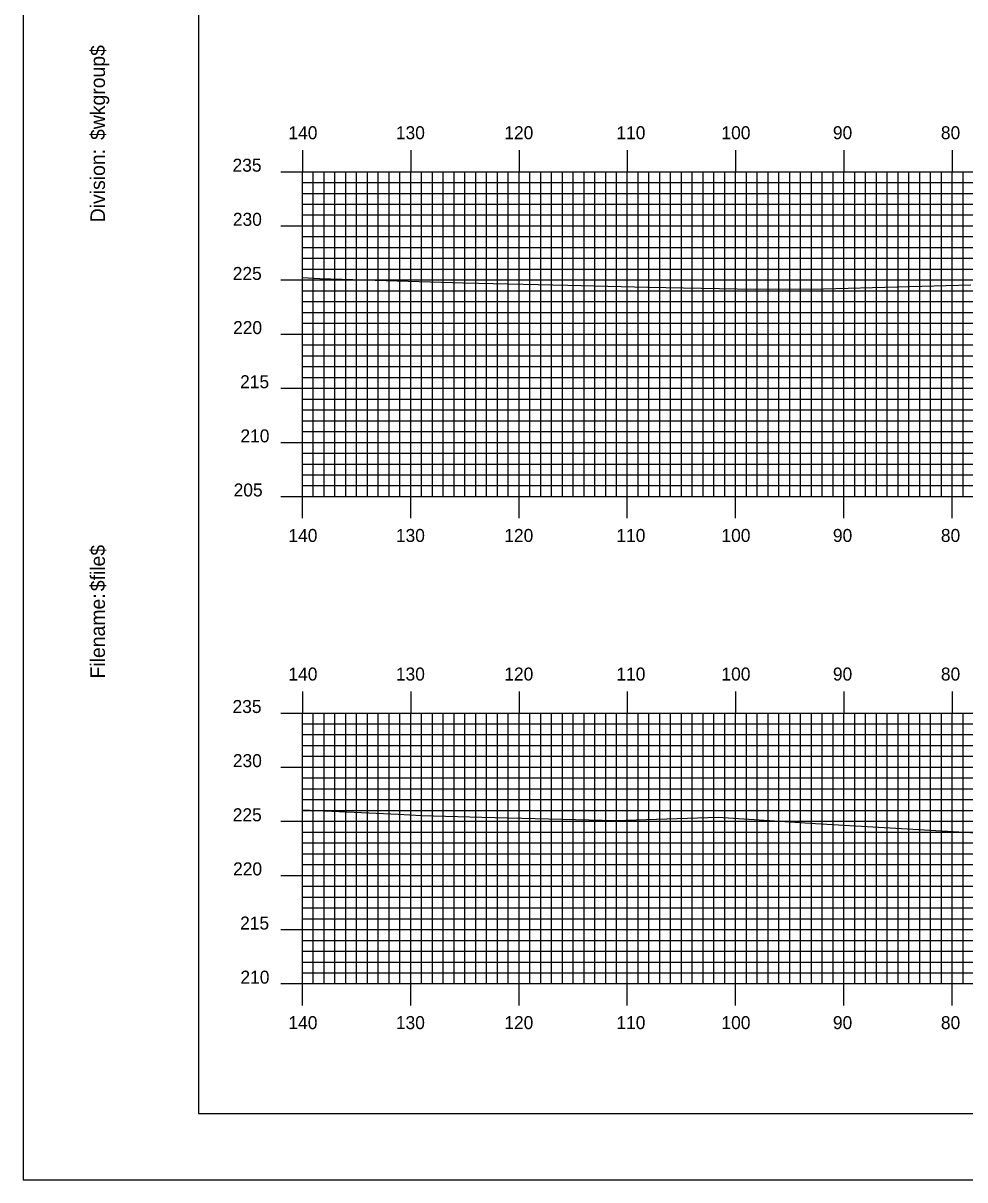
# Model space of a CAD drawing. Extents: x 1820424 to 1820768, y 442591 to 442811.
# Drawn here: x 1820424.4 to 1820511.4, y 442590.5 to 442697.4 of the extents above; entities that cross this region are included whole.
import ezdxf

# ---------------------------------------------------------------- set-up
doc = ezdxf.new("R2010")
doc.units = 0
for name, color, linetype in [('BORDER', 7, 'Continuous'), ('H_V ANNOTATION', 7, 'Continuous'), ('MAJOR', 7, 'Continuous'), ('MINOR', 7, 'Continuous'), ('PLOT BOUNDARY', 7, 'Continuous'), ('S_Roadway_Centerline', 7, 'Continuous')]:
    doc.layers.add(name, color=color, linetype=linetype)

msp = doc.modelspace()

# ---------------------------------------------------------------- linework, layer by layer
at = {"layer": 'BORDER'}
msp.add_lwpolyline([(1820440.6, 442596.67), (1820760.6, 442596.67), (1820760.6, 442806.67), (1820440.6, 442806.67)], close=True, dxfattribs=at)
at = {"layer": 'MAJOR'}
for p, q in [((1820450.2, 442685.67), (1820450.2, 442683.67)), ((1820460.2, 442685.67), (1820460.2, 442683.67)), ((1820470.2, 442685.67), (1820470.2, 442683.67)), ((1820480.2, 442685.67), (1820480.2, 442683.67)), ((1820490.2, 442685.67), (1820490.2, 442683.67)), ((1820500.2, 442685.67), (1820500.2, 442683.67)), ((1820510.2, 442685.67), (1820510.2, 442683.67)), ((1820448.2, 442683.67), (1820450.2, 442683.67)), ((1820450.2, 442683.67), (1820730.2, 442683.67)), ((1820450.2, 442653.67), (1820450.2, 442683.67)), ((1820450.2, 442653.67), (1820450.2, 442683.67)), ((1820450.2, 442683.67), (1820730.2, 442683.67)), ((1820460.2, 442653.67), (1820460.2, 442683.67)), ((1820470.2, 442653.67), (1820470.2, 442683.67)), ((1820480.2, 442653.67), (1820480.2, 442683.67)), ((1820490.2, 442653.67), (1820490.2, 442683.67)), ((1820500.2, 442653.67), (1820500.2, 442683.67)), ((1820510.2, 442653.67), (1820510.2, 442683.67)), ((1820448.2, 442678.67), (1820450.2, 442678.67)), ((1820450.2, 442678.67), (1820730.2, 442678.67)), ((1820448.2, 442673.67), (1820450.2, 442673.67)), ((1820450.2, 442673.67), (1820730.2, 442673.67)), ((1820448.2, 442668.67), (1820450.2, 442668.67)), ((1820450.2, 442668.67), (1820730.2, 442668.67)), ((1820448.2, 442663.67), (1820450.2, 442663.67)), ((1820450.2, 442663.67), (1820730.2, 442663.67)), ((1820448.2, 442658.67), (1820450.2, 442658.67)), ((1820450.2, 442658.67), (1820730.2, 442658.67)), ((1820448.2, 442653.67), (1820450.2, 442653.67)), ((1820450.2, 442653.67), (1820730.2, 442653.67)), ((1820450.2, 442653.67), (1820730.2, 442653.67)), ((1820450.2, 442651.66), (1820450.2, 442653.67)), ((1820460.2, 442651.66), (1820460.2, 442653.67)), ((1820470.2, 442651.66), (1820470.2, 442653.67)), ((1820480.2, 442651.66), (1820480.2, 442653.67)), ((1820490.2, 442651.66), (1820490.2, 442653.67)), ((1820500.2, 442651.66), (1820500.2, 442653.67)), ((1820510.2, 442651.66), (1820510.2, 442653.67)), ((1820450.2, 442635.67), (1820450.2, 442633.67)), ((1820460.2, 442635.67), (1820460.2, 442633.67)), ((1820470.2, 442635.67), (1820470.2, 442633.67)), ((1820480.2, 442635.67), (1820480.2, 442633.67)), ((1820490.2, 442635.67), (1820490.2, 442633.67)), ((1820500.2, 442635.67), (1820500.2, 442633.67)), ((1820510.2, 442635.67), (1820510.2, 442633.67)), ((1820448.2, 442633.67), (1820450.2, 442633.67)), ((1820450.2, 442633.67), (1820730.2, 442633.67)), ((1820450.2, 442608.67), (1820450.2, 442633.67)), ((1820450.2, 442608.67), (1820450.2, 442633.67)), ((1820450.2, 442633.67), (1820730.2, 442633.67)), ((1820460.2, 442608.67), (1820460.2, 442633.67)), ((1820470.2, 442608.67), (1820470.2, 442633.67)), ((1820480.2, 442608.67), (1820480.2, 442633.67)), ((1820490.2, 442608.67), (1820490.2, 442633.67)), ((1820500.2, 442608.67), (1820500.2, 442633.67)), ((1820510.2, 442608.67), (1820510.2, 442633.67)), ((1820448.2, 442628.67), (1820450.2, 442628.67)), ((1820450.2, 442628.67), (1820730.2, 442628.67)), ((1820448.2, 442623.67), (1820450.2, 442623.67)), ((1820450.2, 442623.67), (1820730.2, 442623.67)), ((1820448.2, 442618.67), (1820450.2, 442618.67)), ((1820450.2, 442618.67), (1820730.2, 442618.67)), ((1820448.2, 442613.67), (1820450.2, 442613.67)), ((1820450.2, 442613.67), (1820730.2, 442613.67)), ((1820448.2, 442608.67), (1820450.2, 442608.67)), ((1820450.2, 442608.67), (1820730.2, 442608.67)), ((1820450.2, 442608.67), (1820730.2, 442608.67)), ((1820450.2, 442606.66), (1820450.2, 442608.67)), ((1820460.2, 442606.66), (1820460.2, 442608.67)), ((1820470.2, 442606.66), (1820470.2, 442608.67)), ((1820480.2, 442606.66), (1820480.2, 442608.67)), ((1820490.2, 442606.66), (1820490.2, 442608.67)), ((1820500.2, 442606.66), (1820500.2, 442608.67)), ((1820510.2, 442606.66), (1820510.2, 442608.67))]:
    msp.add_line(p, q, dxfattribs=at)
at = {"layer": 'MINOR'}
for p, q in [((1820451.2, 442653.67), (1820451.2, 442683.67)), ((1820452.2, 442653.67), (1820452.2, 442683.67)), ((1820453.2, 442653.67), (1820453.2, 442683.67)), ((1820454.2, 442653.67), (1820454.2, 442683.67)), ((1820455.2, 442653.67), (1820455.2, 442683.67)), ((1820456.2, 442653.67), (1820456.2, 442683.67)), ((1820457.2, 442653.67), (1820457.2, 442683.67)), ((1820458.2, 442653.67), (1820458.2, 442683.67)), ((1820459.2, 442653.67), (1820459.2, 442683.67)), ((1820461.2, 442653.67), (1820461.2, 442683.67)), ((1820462.2, 442653.67), (1820462.2, 442683.67)), ((1820463.2, 442653.67), (1820463.2, 442683.67)), ((1820464.2, 442653.67), (1820464.2, 442683.67)), ((1820465.2, 442653.67), (1820465.2, 442683.67)), ((1820466.2, 442653.67), (1820466.2, 442683.67)), ((1820467.2, 442653.67), (1820467.2, 442683.67)), ((1820468.2, 442653.67), (1820468.2, 442683.67)), ((1820469.2, 442653.67), (1820469.2, 442683.67)), ((1820471.2, 442653.67), (1820471.2, 442683.67)), ((1820472.2, 442653.67), (1820472.2, 442683.67)), ((1820473.2, 442653.67), (1820473.2, 442683.67)), ((1820474.2, 442653.67), (1820474.2, 442683.67)), ((1820475.2, 442653.67), (1820475.2, 442683.67)), ((1820476.2, 442653.67), (1820476.2, 442683.67)), ((1820477.2, 442653.67), (1820477.2, 442683.67)), ((1820478.2, 442653.67), (1820478.2, 442683.67)), ((1820479.2, 442653.67), (1820479.2, 442683.67)), ((1820481.2, 442653.67), (1820481.2, 442683.67)), ((1820482.2, 442653.67), (1820482.2, 442683.67)), ((1820483.2, 442653.67), (1820483.2, 442683.67)), ((1820484.2, 442653.67), (1820484.2, 442683.67)), ((1820485.2, 442653.67), (1820485.2, 442683.67)), ((1820486.2, 442653.67), (1820486.2, 442683.67)), ((1820487.2, 442653.67), (1820487.2, 442683.67)), ((1820488.2, 442653.67), (1820488.2, 442683.67)), ((1820489.2, 442653.67), (1820489.2, 442683.67)), ((1820491.2, 442653.67), (1820491.2, 442683.67)), ((1820492.2, 442653.67), (1820492.2, 442683.67)), ((1820493.2, 442653.67), (1820493.2, 442683.67)), ((1820494.2, 442653.67), (1820494.2, 442683.67)), ((1820495.2, 442653.67), (1820495.2, 442683.67)), ((1820496.2, 442653.67), (1820496.2, 442683.67)), ((1820497.2, 442653.67), (1820497.2, 442683.67)), ((1820498.2, 442653.67), (1820498.2, 442683.67)), ((1820499.2, 442653.67), (1820499.2, 442683.67)), ((1820501.2, 442653.67), (1820501.2, 442683.67)), ((1820502.2, 442653.67), (1820502.2, 442683.67)), ((1820503.2, 442653.67), (1820503.2, 442683.67)), ((1820504.2, 442653.67), (1820504.2, 442683.67)), ((1820505.2, 442653.67), (1820505.2, 442683.67)), ((1820506.2, 442653.67), (1820506.2, 442683.67)), ((1820507.2, 442653.67), (1820507.2, 442683.67)), ((1820508.2, 442653.67), (1820508.2, 442683.67)), ((1820509.2, 442653.67), (1820509.2, 442683.67)), ((1820511.2, 442653.67), (1820511.2, 442683.67)), ((1820450.2, 442682.67), (1820730.2, 442682.67)), ((1820450.2, 442682.67), (1820452.21, 442682.67)), ((1820450.2, 442681.67), (1820730.2, 442681.67)), ((1820450.2, 442681.67), (1820452.21, 442681.67)), ((1820450.2, 442680.67), (1820730.2, 442680.67)), ((1820450.2, 442680.67), (1820452.21, 442680.67)), ((1820450.2, 442679.67), (1820730.2, 442679.67)), ((1820450.2, 442679.67), (1820452.21, 442679.67)), ((1820450.2, 442677.67), (1820730.2, 442677.67)), ((1820450.2, 442677.67), (1820452.21, 442677.67)), ((1820450.2, 442676.67), (1820730.2, 442676.67)), ((1820450.2, 442676.67), (1820452.21, 442676.67)), ((1820450.2, 442675.67), (1820730.2, 442675.67)), ((1820450.2, 442675.67), (1820452.21, 442675.67)), ((1820450.2, 442674.67), (1820730.2, 442674.67)), ((1820450.2, 442674.67), (1820452.21, 442674.67)), ((1820450.2, 442672.67), (1820730.2, 442672.67)), ((1820450.2, 442672.67), (1820452.21, 442672.67)), ((1820450.2, 442671.67), (1820730.2, 442671.67)), ((1820450.2, 442671.67), (1820452.21, 442671.67)), ((1820450.2, 442670.67), (1820730.2, 442670.67)), ((1820450.2, 442670.67), (1820452.21, 442670.67)), ((1820450.2, 442669.67), (1820730.2, 442669.67)), ((1820450.2, 442669.67), (1820452.21, 442669.67)), ((1820450.2, 442667.67), (1820730.2, 442667.67)), ((1820450.2, 442667.67), (1820452.21, 442667.67)), ((1820450.2, 442666.67), (1820730.2, 442666.67)), ((1820450.2, 442666.67), (1820452.21, 442666.67)), ((1820450.2, 442665.67), (1820730.2, 442665.67)), ((1820450.2, 442665.67), (1820452.21, 442665.67)), ((1820450.2, 442664.67), (1820730.2, 442664.67)), ((1820450.2, 442664.67), (1820452.21, 442664.67)), ((1820450.2, 442662.67), (1820730.2, 442662.67)), ((1820450.2, 442662.67), (1820452.21, 442662.67)), ((1820450.2, 442661.67), (1820730.2, 442661.67)), ((1820450.2, 442661.67), (1820452.21, 442661.67)), ((1820450.2, 442660.67), (1820730.2, 442660.67)), ((1820450.2, 442660.67), (1820452.21, 442660.67)), ((1820450.2, 442659.67), (1820730.2, 442659.67)), ((1820450.2, 442659.67), (1820452.21, 442659.67)), ((1820450.2, 442657.67), (1820730.2, 442657.67)), ((1820450.2, 442657.67), (1820452.21, 442657.67)), ((1820450.2, 442656.67), (1820730.2, 442656.67)), ((1820450.2, 442656.67), (1820452.21, 442656.67)), ((1820450.2, 442655.67), (1820730.2, 442655.67)), ((1820450.2, 442655.67), (1820452.21, 442655.67)), ((1820450.2, 442654.67), (1820730.2, 442654.67)), ((1820450.2, 442654.67), (1820452.21, 442654.67)), ((1820451.2, 442608.67), (1820451.2, 442633.67)), ((1820452.2, 442608.67), (1820452.2, 442633.67)), ((1820453.2, 442608.67), (1820453.2, 442633.67)), ((1820454.2, 442608.67), (1820454.2, 442633.67)), ((1820455.2, 442608.67), (1820455.2, 442633.67)), ((1820456.2, 442608.67), (1820456.2, 442633.67)), ((1820457.2, 442608.67), (1820457.2, 442633.67)), ((1820458.2, 442608.67), (1820458.2, 442633.67)), ((1820459.2, 442608.67), (1820459.2, 442633.67)), ((1820461.2, 442608.67), (1820461.2, 442633.67)), ((1820462.2, 442608.67), (1820462.2, 442633.67)), ((1820463.2, 442608.67), (1820463.2, 442633.67)), ((1820464.2, 442608.67), (1820464.2, 442633.67)), ((1820465.2, 442608.67), (1820465.2, 442633.67)), ((1820466.2, 442608.67), (1820466.2, 442633.67)), ((1820467.2, 442608.67), (1820467.2, 442633.67)), ((1820468.2, 442608.67), (1820468.2, 442633.67)), ((1820469.2, 442608.67), (1820469.2, 442633.67)), ((1820471.2, 442608.67), (1820471.2, 442633.67)), ((1820472.2, 442608.67), (1820472.2, 442633.67)), ((1820473.2, 442608.67), (1820473.2, 442633.67)), ((1820474.2, 442608.67), (1820474.2, 442633.67)), ((1820475.2, 442608.67), (1820475.2, 442633.67)), ((1820476.2, 442608.67), (1820476.2, 442633.67)), ((1820477.2, 442608.67), (1820477.2, 442633.67)), ((1820478.2, 442608.67), (1820478.2, 442633.67)), ((1820479.2, 442608.67), (1820479.2, 442633.67)), ((1820481.2, 442608.67), (1820481.2, 442633.67)), ((1820482.2, 442608.67), (1820482.2, 442633.67)), ((1820483.2, 442608.67), (1820483.2, 442633.67)), ((1820484.2, 442608.67), (1820484.2, 442633.67)), ((1820485.2, 442608.67), (1820485.2, 442633.67)), ((1820486.2, 442608.67), (1820486.2, 442633.67)), ((1820487.2, 442608.67), (1820487.2, 442633.67)), ((1820488.2, 442608.67), (1820488.2, 442633.67)), ((1820489.2, 442608.67), (1820489.2, 442633.67)), ((1820491.2, 442608.67), (1820491.2, 442633.67)), ((1820492.2, 442608.67), (1820492.2, 442633.67)), ((1820493.2, 442608.67), (1820493.2, 442633.67)), ((1820494.2, 442608.67), (1820494.2, 442633.67)), ((1820495.2, 442608.67), (1820495.2, 442633.67)), ((1820496.2, 442608.67), (1820496.2, 442633.67)), ((1820497.2, 442608.67), (1820497.2, 442633.67)), ((1820498.2, 442608.67), (1820498.2, 442633.67)), ((1820499.2, 442608.67), (1820499.2, 442633.67)), ((1820501.2, 442608.67), (1820501.2, 442633.67)), ((1820502.2, 442608.67), (1820502.2, 442633.67)), ((1820503.2, 442608.67), (1820503.2, 442633.67)), ((1820504.2, 442608.67), (1820504.2, 442633.67)), ((1820505.2, 442608.67), (1820505.2, 442633.67)), ((1820506.2, 442608.67), (1820506.2, 442633.67)), ((1820507.2, 442608.67), (1820507.2, 442633.67)), ((1820508.2, 442608.67), (1820508.2, 442633.67)), ((1820509.2, 442608.67), (1820509.2, 442633.67)), ((1820511.2, 442608.67), (1820511.2, 442633.67)), ((1820450.2, 442632.67), (1820730.2, 442632.67)), ((1820450.2, 442632.67), (1820452.21, 442632.67)), ((1820450.2, 442631.67), (1820730.2, 442631.67)), ((1820450.2, 442631.67), (1820452.21, 442631.67)), ((1820450.2, 442630.67), (1820730.2, 442630.67)), ((1820450.2, 442630.67), (1820452.21, 442630.67)), ((1820450.2, 442629.67), (1820730.2, 442629.67)), ((1820450.2, 442629.67), (1820452.21, 442629.67)), ((1820450.2, 442627.67), (1820730.2, 442627.67)), ((1820450.2, 442627.67), (1820452.21, 442627.67)), ((1820450.2, 442626.67), (1820730.2, 442626.67)), ((1820450.2, 442626.67), (1820452.21, 442626.67)), ((1820450.2, 442625.67), (1820730.2, 442625.67)), ((1820450.2, 442625.67), (1820452.21, 442625.67)), ((1820450.2, 442624.67), (1820730.2, 442624.67)), ((1820450.2, 442624.67), (1820452.21, 442624.67)), ((1820450.2, 442622.67), (1820730.2, 442622.67)), ((1820450.2, 442622.67), (1820452.21, 442622.67)), ((1820450.2, 442621.67), (1820730.2, 442621.67)), ((1820450.2, 442621.67), (1820452.21, 442621.67)), ((1820450.2, 442620.67), (1820730.2, 442620.67)), ((1820450.2, 442620.67), (1820452.21, 442620.67)), ((1820450.2, 442619.67), (1820730.2, 442619.67)), ((1820450.2, 442619.67), (1820452.21, 442619.67)), ((1820450.2, 442617.67), (1820730.2, 442617.67)), ((1820450.2, 442617.67), (1820452.21, 442617.67)), ((1820450.2, 442616.67), (1820730.2, 442616.67)), ((1820450.2, 442616.67), (1820452.21, 442616.67)), ((1820450.2, 442615.67), (1820730.2, 442615.67)), ((1820450.2, 442615.67), (1820452.21, 442615.67)), ((1820450.2, 442614.67), (1820730.2, 442614.67)), ((1820450.2, 442614.67), (1820452.21, 442614.67)), ((1820450.2, 442612.67), (1820730.2, 442612.67)), ((1820450.2, 442612.67), (1820452.21, 442612.67)), ((1820450.2, 442611.67), (1820730.2, 442611.67)), ((1820450.2, 442611.67), (1820452.21, 442611.67)), ((1820450.2, 442610.67), (1820730.2, 442610.67)), ((1820450.2, 442610.67), (1820452.21, 442610.67)), ((1820450.2, 442609.67), (1820730.2, 442609.67)), ((1820450.2, 442609.67), (1820452.21, 442609.67))]:
    msp.add_line(p, q, dxfattribs=at)
at = {"layer": 'PLOT BOUNDARY'}
msp.add_lwpolyline([(1820424.42, 442590.55), (1820764.42, 442590.55), (1820764.42, 442810.55), (1820424.42, 442810.55)], close=True, dxfattribs=at)
at = {"layer": 'S_Roadway_Centerline'}
for points in [[(1820450.2, 442673.89), (1820451.81, 442673.81), (1820465.06, 442673.41), (1820474.7, 442673.19), (1820482.1, 442673), (1820492, 442672.81), (1820498.3, 442672.85), (1820511.91, 442673.22)], [(1820450.2, 442624.74), (1820459.03, 442624.34), (1820461.2, 442624.2), (1820466.78, 442624.05), (1820479.11, 442623.73), (1820488.6, 442624.04), (1820497.56, 442623.45), (1820526.17, 442621.81)]]:
    msp.add_lwpolyline(points, dxfattribs=at)

# ---------------------------------------------------------------- texts
at = {"layer": 'BORDER'}
for s, p in [('$wkgroup$', (1820431.97, 442686.6)), ('Division:', (1820431.97, 442679)), ('$file$', (1820431.97, 442644.92)), ('Filename:', (1820431.97, 442636.86))]:
    msp.add_text(s, height=1.339, rotation=90, dxfattribs=at).set_placement(p)
at = {"layer": 'H_V ANNOTATION'}
for s, p in [('140', (1820448.91, 442686.67)), ('130', (1820458.83, 442686.67)), ('120', (1820468.84, 442686.67)), ('110', (1820479.19, 442686.67)), ('100', (1820488.89, 442686.67)), ('90', (1820499.18, 442686.67)), ('80', (1820509.15, 442686.67)), ('235', (1820443.75, 442683.67)), ('230', (1820443.78, 442678.67)), ('225', (1820443.77, 442673.67)), ('220', (1820443.8, 442668.67)), ('215', (1820444.45, 442663.67)), ('210', (1820444.48, 442658.67)), ('205', (1820443.85, 442653.67)), ('140', (1820448.91, 442649.47)), ('130', (1820458.83, 442649.47)), ('120', (1820468.84, 442649.47)), ('110', (1820479.19, 442649.47)), ('100', (1820488.89, 442649.47)), ('90', (1820499.18, 442649.47)), ('80', (1820509.15, 442649.47)), ('140', (1820448.91, 442636.67)), ('130', (1820458.83, 442636.67)), ('120', (1820468.84, 442636.67)), ('110', (1820479.19, 442636.67)), ('100', (1820488.89, 442636.67)), ('90', (1820499.18, 442636.67)), ('80', (1820509.15, 442636.67)), ('235', (1820443.75, 442633.67)), ('230', (1820443.78, 442628.67)), ('225', (1820443.77, 442623.67)), ('220', (1820443.8, 442618.67)), ('215', (1820444.45, 442613.67)), ('210', (1820444.48, 442608.67)), ('140', (1820448.91, 442604.47)), ('130', (1820458.83, 442604.47)), ('120', (1820468.84, 442604.47)), ('110', (1820479.19, 442604.47)), ('100', (1820488.89, 442604.47)), ('90', (1820499.18, 442604.47)), ('80', (1820509.15, 442604.47))]:
    msp.add_text(s, height=1.2, dxfattribs=at).set_placement(p)
at = {"layer": 'MAJOR'}
for p in [(1820450.19, 442653.67), (1820450.19, 442608.67)]:
    msp.add_text('-', height=0.012, dxfattribs=at).set_placement(p)

doc.saveas('drawing.dxf')
